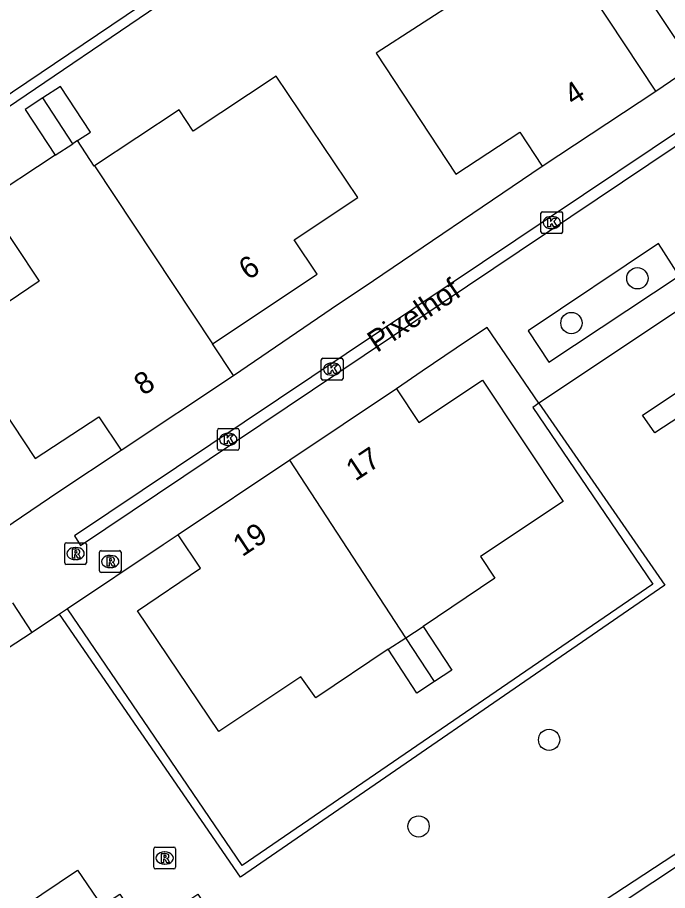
# Model space of a CAD drawing. Extents: x 158797 to 159887, y 384318 to 385255.
# Drawn here: x 159048.69 to 159078.58, y 384605.03 to 384645.19 of the extents above; entities that cross this region are included whole.
import ezdxf

# ---------------------------------------------------------------- set-up
doc = ezdxf.new("R2010")
doc.units = 0
for name, color, linetype in [('IMGEO_Boom', 7, 'Continuous'), ('IMGEO_Haag', 7, 'Continuous'), ('IMGEO_Kolk', 7, 'Continuous'), ('IMGEO_Openbare_ruimte_label', 7, 'Continuous'), ('IMGEO_Pand', 7, 'Continuous'), ('IMGEO_Pand_nummerreeks', 7, 'Continuous'), ('IMGEO_Rijbaan_lokaal_open', 7, 'Continuous'), ('IMGEO_Rioolput', 7, 'Continuous'), ('IMGEO_Voetpad_gesloten', 7, 'Continuous')]:
    doc.layers.add(name, color=color, linetype=linetype)

msp = doc.modelspace()

# ---------------------------------------------------------------- linework, layer by layer
at = {"layer": 'IMGEO_Boom'}
for centre in [(159077.198, 384633.192), (159074.166, 384631.133), (159073.138, 384611.962), (159067.135, 384607.977)]:
    msp.add_circle(centre, 0.489, dxfattribs=at)
at = {"layer": 'IMGEO_Haag'}
for points in [[(159074.64, 384658.987), (159074.434, 384659.327), (159072.046, 384657.677), (159028.116, 384628.032), (159038.03, 384613.181), (159038.222, 384613.33)], [(159038.372, 384613.43), (159028.729, 384627.821), (159074.64, 384658.987)], [(159072.658, 384627.446), (159078.461, 384619.069), (159058.95, 384605.65), (159050.633, 384617.743)], [(159072.658, 384627.446), (159072.39, 384627.254), (159077.911, 384619.118), (159059.027, 384606.175), (159050.987, 384617.98)], [(159049.365, 384616.904), (159044.054, 384613.436)], [(159087.836, 384612.005), (159087.593, 384612.37), (159070.636, 384601.253), (159076.982, 384592.004), (159082.614, 384595.522), (159088.371, 384587.681)], [(159087.836, 384612.005), (159071.316, 384601.011), (159077.121, 384592.427), (159082.677, 384595.88), (159088.369, 384588.11)]]:
    msp.add_lwpolyline(points, dxfattribs=at)
at = {"layer": 'IMGEO_Kolk'}
for p, q in [((159072.76, 384635.329), (159072.76, 384636.181)), ((159072.835, 384636.255), (159073.687, 384636.255)), ((159073.761, 384636.181), (159073.761, 384635.329)), ((159073.248, 384636.035), (159073.273, 384636.035)), ((159073.271, 384635.475), (159073.246, 384635.475)), ((159073.687, 384635.255), (159072.835, 384635.255)), ((159062.664, 384628.587), (159062.664, 384629.439)), ((159062.739, 384629.513), (159063.591, 384629.513)), ((159063.665, 384629.439), (159063.665, 384628.587)), ((159063.152, 384629.293), (159063.177, 384629.293)), ((159063.591, 384628.513), (159062.739, 384628.513)), ((159063.175, 384628.733), (159063.15, 384628.733)), ((159057.885, 384625.358), (159057.885, 384626.21)), ((159057.96, 384626.284), (159058.812, 384626.284)), ((159058.886, 384626.21), (159058.886, 384625.358)), ((159058.373, 384626.064), (159058.398, 384626.064)), ((159058.396, 384625.504), (159058.371, 384625.504)), ((159058.812, 384625.284), (159057.96, 384625.284))]:
    msp.add_line(p, q, dxfattribs=at)
for points in [[(159072.76, 384635.329), (159072.76, 384636.181)], [(159072.835, 384636.255), (159073.687, 384636.255)], [(159073.761, 384636.181), (159073.761, 384635.329)], [(159073.081, 384635.955), (159073.204, 384635.955), (159073.204, 384635.804), (159073.334, 384635.955), (159073.498, 384635.955), (159073.352, 384635.804), (159073.505, 384635.555), (159073.353, 384635.555), (159073.268, 384635.719), (159073.204, 384635.652), (159073.204, 384635.555), (159073.081, 384635.555), (159073.081, 384635.955)], [(159073.687, 384635.255), (159072.835, 384635.255)], [(159062.664, 384628.587), (159062.664, 384629.439)], [(159062.739, 384629.513), (159063.591, 384629.513)], [(159063.665, 384629.439), (159063.665, 384628.587)], [(159062.985, 384629.213), (159063.108, 384629.213), (159063.108, 384629.062), (159063.238, 384629.213), (159063.402, 384629.213), (159063.256, 384629.062), (159063.409, 384628.813), (159063.257, 384628.813), (159063.172, 384628.977), (159063.108, 384628.91), (159063.108, 384628.813), (159062.985, 384628.813), (159062.985, 384629.213)], [(159063.591, 384628.513), (159062.739, 384628.513)], [(159057.885, 384625.358), (159057.885, 384626.21)], [(159057.96, 384626.284), (159058.812, 384626.284)], [(159058.886, 384626.21), (159058.886, 384625.358)], [(159058.206, 384625.984), (159058.329, 384625.984), (159058.329, 384625.833), (159058.459, 384625.984), (159058.623, 384625.984), (159058.477, 384625.833), (159058.63, 384625.584), (159058.478, 384625.584), (159058.393, 384625.748), (159058.329, 384625.681), (159058.329, 384625.584), (159058.206, 384625.584), (159058.206, 384625.984)], [(159058.812, 384625.284), (159057.96, 384625.284)]]:
    msp.add_lwpolyline(points, dxfattribs=at)
for centre, start, end in [((159072.837, 384636.179), 91.552, 178.448), ((159072.837, 384636.179), 91.552, 178.448), ((159073.685, 384636.179), 1.552, 88.448), ((159073.685, 384636.179), 1.552, 88.448), ((159072.837, 384635.331), 181.552, 268.448), ((159072.837, 384635.331), 181.552, 268.448), ((159073.685, 384635.331), 271.552, 358.448), ((159073.685, 384635.331), 271.552, 358.448), ((159062.741, 384629.437), 91.552, 178.448), ((159062.741, 384629.437), 91.552, 178.448), ((159063.589, 384629.437), 1.552, 88.448), ((159063.589, 384629.437), 1.552, 88.448), ((159062.741, 384628.589), 181.552, 268.448), ((159062.741, 384628.589), 181.552, 268.448), ((159063.589, 384628.589), 271.552, 358.448), ((159063.589, 384628.589), 271.552, 358.448), ((159057.962, 384626.208), 91.552, 178.448), ((159057.962, 384626.208), 91.552, 178.448), ((159058.81, 384626.208), 1.552, 88.448), ((159058.81, 384626.208), 1.552, 88.448), ((159057.962, 384625.36), 181.552, 268.448), ((159057.962, 384625.36), 181.552, 268.448), ((159058.81, 384625.36), 271.552, 358.448), ((159058.81, 384625.36), 271.552, 358.448)]:
    msp.add_arc(centre, 0.0765, start, end, dxfattribs=at)
for centre, major_axis, ratio, start_param, end_param in [((159073.247, 384635.755), (-0.387, 0.002), 0.722429, 4.712389, 7.853982), ((159073.272, 384635.755), (-0.39, 0.002), 0.717154, 1.570796, 4.712389), ((159063.151, 384629.013), (-0.387, 0.002), 0.722429, 4.712389, 7.853982), ((159063.176, 384629.013), (-0.39, 0.002), 0.717154, 1.570796, 4.712389), ((159058.372, 384625.784), (-0.387, 0.002), 0.722429, 4.712389, 7.853982), ((159058.397, 384625.784), (-0.39, 0.002), 0.717154, 1.570796, 4.712389)]:
    msp.add_ellipse(centre, major_axis=major_axis, ratio=ratio, start_param=start_param, end_param=end_param, dxfattribs=at)
at = {"layer": 'IMGEO_Pand'}
for points in [[(159070.065, 384652.134), (159066.462, 384649.786), (159066.719, 384649.392), (159066.861, 384649.485), (159069.078, 384646.082), (159065.184, 384643.544), (159068.855, 384637.984), (159071.785, 384639.918), (159072.82, 384638.349)], [(159078.044, 384641.798), (159074.44, 384647.256)], [(159057.656, 384630.182), (159062.468, 384633.385), (159061.42, 384634.958), (159064.349, 384636.907), (159060.593, 384642.495), (159056.776, 384639.96), (159056.124, 384640.943), (159052.239, 384638.367)], [(159051.452, 384639.525), (159052.047, 384639.913), (159050.678, 384642.017), (159049.864, 384641.488)], [(159072.82, 384638.349), (159078.044, 384641.798)], [(159049.864, 384641.488), (159049.049, 384640.958), (159050.433, 384638.855)], [(159051.233, 384639.381), (159049.864, 384641.488)], [(159050.433, 384638.855), (159051.233, 384639.381)], [(159051.452, 384639.525), (159051.233, 384639.381)], [(159052.239, 384638.367), (159052.216, 384638.352), (159051.452, 384639.525)], [(159050.433, 384638.855), (159047.117, 384636.683), (159047.338, 384636.359), (159047.443, 384636.432), (159049.695, 384633.062), (159045.826, 384630.454), (159049.515, 384624.898), (159052.429, 384626.817), (159053.468, 384625.292)], [(159052.239, 384638.367), (159057.656, 384630.182)], [(159058.626, 384628.725), (159057.656, 384630.182)], [(159053.468, 384625.292), (159058.626, 384628.725)], [(159066.125, 384628.106), (159061.214, 384624.822)], [(159066.125, 384628.106), (159067.155, 384626.557), (159070.078, 384628.501), (159073.783, 384622.932), (159069.978, 384620.4), (159070.649, 384619.405), (159067.347, 384617.182)], [(159061.214, 384624.822), (159056.089, 384621.395)], [(159066.544, 384616.657), (159061.214, 384624.822)], [(159065.74, 384616.131), (159062.416, 384613.899), (159061.727, 384614.866), (159057.953, 384612.346), (159054.206, 384617.896), (159057.107, 384619.855), (159056.089, 384621.395)], [(159066.544, 384616.657), (159067.347, 384617.182)], [(159067.347, 384617.182), (159068.664, 384615.164), (159067.861, 384614.64)], [(159065.74, 384616.131), (159066.544, 384616.657)], [(159067.861, 384614.64), (159066.544, 384616.657)], [(159067.861, 384614.64), (159067.057, 384614.115), (159065.74, 384616.131)]]:
    msp.add_lwpolyline(points, dxfattribs=at)
at = {"layer": 'IMGEO_Rijbaan_lokaal_open'}
for points in [[(159078.044, 384641.798), (159079.779, 384642.984), (159076.202, 384648.351)], [(159051.323, 384621.345), (159051.588, 384620.908), (159081.264, 384640.811), (159080.983, 384641.239), (159051.323, 384621.345)], [(159058.626, 384628.725), (159063.449, 384632.011), (159064.596, 384632.772), (159072.82, 384638.349)], [(159072.168, 384630.775), (159073.13, 384629.336), (159079.119, 384633.309), (159078.169, 384634.786), (159072.168, 384630.775)], [(159079.875, 384632.241), (159072.658, 384627.446)], [(159072.658, 384627.446), (159070.296, 384630.934), (159069.385, 384630.332), (159067.304, 384628.917), (159066.125, 384628.106)], [(159046.764, 384620.801), (159050.601, 384623.386), (159053.468, 384625.292)], [(159056.089, 384621.395), (159055.392, 384620.925), (159050.987, 384617.98)], [(159049.365, 384616.904), (159048.477, 384618.263)], [(159050.633, 384617.743), (159049.369, 384616.898), (159049.365, 384616.904)], [(159050.987, 384617.98), (159050.633, 384617.743)]]:
    msp.add_lwpolyline(points, dxfattribs=at)
at = {"layer": 'IMGEO_Rioolput'}
for p, q in [((159050.866, 384620.104), (159050.866, 384620.956)), ((159050.941, 384621.03), (159051.793, 384621.03)), ((159051.867, 384620.956), (159051.867, 384620.104)), ((159051.354, 384620.81), (159051.379, 384620.81)), ((159052.46, 384619.737), (159052.46, 384620.589)), ((159052.535, 384620.663), (159053.387, 384620.663)), ((159053.461, 384620.589), (159053.461, 384619.737)), ((159051.377, 384620.25), (159051.352, 384620.25)), ((159052.948, 384620.443), (159052.973, 384620.443)), ((159051.793, 384620.03), (159050.941, 384620.03)), ((159052.971, 384619.883), (159052.946, 384619.883)), ((159053.387, 384619.663), (159052.535, 384619.663)), ((159054.962, 384606.098), (159054.962, 384606.95)), ((159055.037, 384607.024), (159055.889, 384607.024)), ((159055.963, 384606.95), (159055.963, 384606.098)), ((159055.45, 384606.804), (159055.475, 384606.804)), ((159055.889, 384606.024), (159055.037, 384606.024)), ((159055.473, 384606.244), (159055.448, 384606.244))]:
    msp.add_line(p, q, dxfattribs=at)
for points in [[(159050.866, 384620.104), (159050.866, 384620.956)], [(159050.941, 384621.03), (159051.793, 384621.03)], [(159051.867, 384620.956), (159051.867, 384620.104)], [(159051.455, 384620.728), (159051.203, 384620.73), (159051.203, 384620.33)], [(159051.203, 384620.33), (159051.327, 384620.33), (159051.327, 384620.492), (159051.338, 384620.492)], [(159051.381, 384620.649), (159051.327, 384620.649), (159051.327, 384620.568)], [(159051.327, 384620.568), (159051.379, 384620.568)], [(159052.46, 384619.737), (159052.46, 384620.589)], [(159052.535, 384620.663), (159053.387, 384620.663)], [(159053.461, 384620.589), (159053.461, 384619.737)], [(159051.385, 384620.463), (159051.456, 384620.33), (159051.596, 384620.33), (159051.531, 384620.456)], [(159053.049, 384620.361), (159052.797, 384620.363), (159052.797, 384619.963)], [(159052.797, 384619.963), (159052.921, 384619.963), (159052.921, 384620.125), (159052.932, 384620.125)], [(159052.975, 384620.282), (159052.921, 384620.282), (159052.921, 384620.201)], [(159052.921, 384620.201), (159052.973, 384620.201)], [(159052.979, 384620.096), (159053.05, 384619.963), (159053.19, 384619.963), (159053.125, 384620.089)], [(159051.793, 384620.03), (159050.941, 384620.03)], [(159053.387, 384619.663), (159052.535, 384619.663)], [(159054.962, 384606.098), (159054.962, 384606.95)], [(159055.037, 384607.024), (159055.889, 384607.024)], [(159055.963, 384606.95), (159055.963, 384606.098)], [(159055.551, 384606.722), (159055.299, 384606.724), (159055.299, 384606.324)], [(159055.299, 384606.324), (159055.423, 384606.324), (159055.423, 384606.486), (159055.434, 384606.486)], [(159055.477, 384606.643), (159055.423, 384606.643), (159055.423, 384606.562)], [(159055.423, 384606.562), (159055.475, 384606.562)], [(159055.481, 384606.457), (159055.552, 384606.324), (159055.692, 384606.324), (159055.627, 384606.45)], [(159055.889, 384606.024), (159055.037, 384606.024)]]:
    msp.add_lwpolyline(points, dxfattribs=at)
for centre, radius, start, end in [((159050.943, 384620.954), 0.0765, 91.552, 178.448), ((159050.943, 384620.954), 0.0765, 91.552, 178.448), ((159051.791, 384620.954), 0.0765, 1.552, 88.448), ((159051.791, 384620.954), 0.0765, 1.552, 88.448), ((159051.337, 384620.439), 0.0533, 26.0293, 88.6989), ((159051.363, 384620.757), 0.19, 274.7715, 282.9687), ((159051.387, 384620.553), 0.0964, 77.0061, 93.1865), ((159051.401, 384620.61), 0.0378, 276.6634, 79.6772), ((159051.454, 384620.618), 0.109, 350.3612, 89.416), ((159051.452, 384620.618), 0.112, 277.5842, 350.9817), ((159051.436, 384620.403), 0.108, 29.5134, 73.7905), ((159052.537, 384620.587), 0.0765, 91.552, 178.448), ((159052.537, 384620.587), 0.0765, 91.552, 178.448), ((159053.385, 384620.587), 0.0765, 1.552, 88.448), ((159053.385, 384620.587), 0.0765, 1.552, 88.448), ((159050.943, 384620.106), 0.0765, 181.552, 268.448), ((159050.943, 384620.106), 0.0765, 181.552, 268.448), ((159051.791, 384620.106), 0.0765, 271.552, 358.448), ((159051.791, 384620.106), 0.0765, 271.552, 358.448), ((159052.931, 384620.072), 0.0533, 26.0293, 88.6989), ((159052.957, 384620.39), 0.19, 274.7715, 282.9687), ((159052.981, 384620.186), 0.0964, 77.0061, 93.1865), ((159052.995, 384620.243), 0.0378, 276.6634, 79.6772), ((159053.048, 384620.251), 0.109, 350.3612, 89.416), ((159053.046, 384620.251), 0.112, 277.5842, 350.9817), ((159053.03, 384620.036), 0.108, 29.5134, 73.7905), ((159052.537, 384619.739), 0.0765, 181.552, 268.448), ((159052.537, 384619.739), 0.0765, 181.552, 268.448), ((159053.385, 384619.739), 0.0765, 271.552, 358.448), ((159053.385, 384619.739), 0.0765, 271.552, 358.448), ((159055.039, 384606.948), 0.0765, 91.552, 178.448), ((159055.039, 384606.948), 0.0765, 91.552, 178.448), ((159055.887, 384606.948), 0.0765, 1.552, 88.448), ((159055.887, 384606.948), 0.0765, 1.552, 88.448), ((159055.433, 384606.433), 0.0533, 26.0293, 88.6989), ((159055.459, 384606.751), 0.19, 274.7715, 282.9687), ((159055.483, 384606.547), 0.0964, 77.0061, 93.1865), ((159055.497, 384606.604), 0.0378, 276.6634, 79.6772), ((159055.55, 384606.612), 0.109, 350.3612, 89.416), ((159055.548, 384606.612), 0.112, 277.5842, 350.9817), ((159055.532, 384606.397), 0.108, 29.5134, 73.7905), ((159055.039, 384606.1), 0.0765, 181.552, 268.448), ((159055.039, 384606.1), 0.0765, 181.552, 268.448), ((159055.887, 384606.1), 0.0765, 271.552, 358.448), ((159055.887, 384606.1), 0.0765, 271.552, 358.448)]:
    msp.add_arc(centre, radius, start, end, dxfattribs=at)
for centre, major_axis, ratio, start_param, end_param in [((159051.353, 384620.53), (-0.387, 0.002), 0.722429, 4.712389, 7.853982), ((159051.378, 384620.53), (-0.39, 0.002), 0.717154, 1.570796, 4.712389), ((159052.947, 384620.163), (-0.387, 0.002), 0.722429, 4.712389, 7.853982), ((159052.972, 384620.163), (-0.39, 0.002), 0.717154, 1.570796, 4.712389), ((159055.449, 384606.524), (-0.387, 0.002), 0.722429, 4.712389, 7.853982), ((159055.474, 384606.524), (-0.39, 0.002), 0.717154, 1.570796, 4.712389)]:
    msp.add_ellipse(centre, major_axis=major_axis, ratio=ratio, start_param=start_param, end_param=end_param, dxfattribs=at)
at = {"layer": 'IMGEO_Voetpad_gesloten'}
for points in [[(159091.18, 384614.272), (159087.279, 384620.222), (159087.659, 384620.489), (159085.726, 384623.381), (159084.923, 384622.861), (159083.814, 384624.492), (159084.629, 384625.064), (159082.155, 384628.802), (159077.994, 384626.082), (159077.435, 384626.893), (159081.593, 384629.649), (159079.875, 384632.241)], [(159044.054, 384613.436), (159044.228, 384613.182), (159037.615, 384608.714), (159039.816, 384605.41), (159044.001, 384608.156), (159047.314, 384603.188), (159051.455, 384605.973), (159052.578, 384604.324), (159053.4, 384604.861), (159054.5, 384603.213), (159056.994, 384604.867), (159058.651, 384602.367), (159059.496, 384602.965), (159067.874, 384590.535), (159069.539, 384591.642), (159072.876, 384586.683), (159076.198, 384588.909), (159080.104, 384583.132), (159083.425, 384585.352), (159084.526, 384583.696), (159093.592, 384589.775)]]:
    msp.add_lwpolyline(points, dxfattribs=at)

# ---------------------------------------------------------------- texts
at = {"layer": 'IMGEO_Openbare_ruimte_label'}
msp.add_text('Pixelhof', height=1, rotation=34.0395, dxfattribs=at).set_placement((159065.223, 384629.75))
at = {"layer": 'IMGEO_Pand_nummerreeks'}
for s, rotation, p in [('4', 33.2373, (159074.25, 384641.092)), ('6', 33.4493, (159059.299, 384633.079)), ('8', 33.4493, (159054.481, 384627.77)), ('17', 33.5696, (159064.23, 384623.836)), ('19', 33.5696, (159059.029, 384620.358))]:
    msp.add_text(s, height=1, rotation=rotation, dxfattribs=at).set_placement(p)

doc.saveas('drawing.dxf')
